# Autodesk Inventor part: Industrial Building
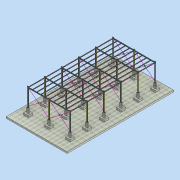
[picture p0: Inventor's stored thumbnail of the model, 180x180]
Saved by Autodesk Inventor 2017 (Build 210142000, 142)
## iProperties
Created: 2018-12
Part Number: Industrial Building
Material: Generic
Document SubType Name: Modeling
Designer: BasilMayyas
Density: 1 g/cm^3
Appearance: Default
Author: BasilMayyas
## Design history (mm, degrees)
derived "Frame0001.iam"
body "Solid1"
node "JIS 350 x 150 x 9 A:1"
node "JIS 350 x 150 x 9 B:1"
node "JIS 350 x 150 x 9 C:1"
node "JIS 250 x 125 x 7.5 AB Tie Beam:1"
node "JIS 250 x 125 x 7.5 BC Tie Beam:1"
node "JIS 350 x 150 x 9 B:2"
node "JIS 350 x 150 x 9 A:2"
node "JIS 350 x 150 x 9 C:2"
node "JIS 350 x 150 x 9 B:3"
node "JIS 350 x 150 x 9 A:3"
node "JIS 350 x 150 x 9 C:3"
node "JIS 350 x 150 x 9 B:4"
node "JIS 350 x 150 x 9 A:4"
node "JIS 350 x 150 x 9 C:4"
node "JIS 350 x 150 x 9 B:5"
node "JIS 350 x 150 x 9 A:5"
node "JIS 350 x 150 x 9 C:5"
node "JIS 350 x 150 x 9 B:6"
node "JIS 350 x 150 x 9 A:6"
node "JIS 350 x 150 x 9 C:6"
node "JIS 250 x 125 x 7.5 AB Tie Beam:2"
node "JIS 250 x 125 x 7.5 AB Tie Beam:3"
node "JIS 250 x 125 x 7.5 AB Tie Beam:4"
node "JIS 250 x 125 x 7.5 AB Tie Beam:5"
node "JIS 250 x 125 x 7.5 AB Tie Beam:6"
node "JIS 250 x 125 x 7.5 BC Tie Beam:2"
node "JIS 250 x 125 x 7.5 BC Tie Beam:3"
node "JIS 250 x 125 x 7.5 BC Tie Beam:4"
node "JIS 250 x 125 x 7.5 BC Tie Beam:5"
node "JIS 250 x 125 x 7.5 BC Tie Beam:6"
node "I350 Base Plate.ipt:1"
node "I350 Base Plate.ipt:2"
node "I350 Base Plate.ipt:3"
node "I350 Base Plate.ipt:4"
node "I350 Base Plate.ipt:5"
node "I350 Base Plate.ipt:6"
node "I350 Base Plate.ipt:7"
node "I350 Base Plate.ipt:8"
node "I350 Base Plate.ipt:9"
node "I350 Base Plate.ipt:10"
node "I350 Base Plate.ipt:11"
node "I350 Base Plate.ipt:12"
node "I350 Base Plate.ipt:13"
node "I350 Base Plate.ipt:14"
node "I350 Base Plate.ipt:15"
node "I350 Base Plate.ipt:16"
node "I350 Base Plate.ipt:17"
node "I350 Base Plate.ipt:18"
node "I350 Base Plate.ipt:19"
node "I350 Base Plate.ipt:20"
node "I350 Base Plate.ipt:21"
node "I350 Base Plate.ipt:22"
node "I350 Base Plate.ipt:23"
node "I350 Base Plate.ipt:24"
node "I350 Base Plate.ipt:25"
node "I350 Base Plate.ipt:26"
node "I350 Base Plate.ipt:27"
node "I350 Base Plate.ipt:28"
node "I350 Base Plate.ipt:29"
node "I350 Base Plate.ipt:30"
node "I350 Base Plate.ipt:31"
node "I350 Base Plate.ipt:32"
node "I350 Base Plate.ipt:33"
node "I350 Base Plate.ipt:34"
node "I350 Base Plate.ipt:35"
node "I350 Base Plate.ipt:36"
node "JIS 200 x 100 x 7 Roof Support Beam:1"
node "JIS 200 x 100 x 7 Roof Support Beam:2"
node "JIS 200 x 100 x 7 Roof Support Beam:3"
node "JIS 200 x 100 x 7 Roof Support Beam:4"
node "JIS 200 x 100 x 7 Roof Support Beam:5"
node "JIS 200 x 100 x 7 Roof Support Beam:6"
node "JIS 200 x 100 x 7 Roof Support Beam:7"
node "JIS 200 x 100 x 7 Roof Support Beam:8"
node "JIS 200 x 100 x 7 Roof Support Beam:9"
node "JIS 200 x 100 x 7 Roof Support Beam:10"
node "JIS 200 x 100 x 7 Roof Support Beam:11"
node "JIS 200 x 100 x 7 Roof Support Beam:12"
node "JIS 200 x 100 x 7 Roof Support Beam:13"
node "JIS 200 x 100 x 7 Roof Support Beam:14"
node "JIS 200 x 100 x 7 Roof Support Beam:15"
node "JIS 200 x 100 x 7 Roof Support Beam:16"
node "JIS 200 x 100 x 7 Roof Support Beam:17"
node "JIS 200 x 100 x 7 Roof Support Beam:18"
node "JIS 200 x 100 x 7 Roof Support Beam:19"
node "JIS 200 x 100 x 7 Roof Support Beam:20"
node "JIS 200 x 100 x 7 Roof Support Beam:21"
node "JIS 200 x 100 x 7 Roof Support Beam:22"
node "JIS 200 x 100 x 7 Roof Support Beam:23"
node "JIS 200 x 100 x 7 Roof Support Beam:24"
node "JIS 200 x 100 x 7 Roof Support Beam:25"
node "JIS 200 x 100 x 7 Roof Support Beam:26"
node "JIS 200 x 100 x 7 Roof Support Beam:27"
node "JIS 200 x 100 x 7 Roof Support Beam:28"
node "JIS 200 x 100 x 7 Roof Support Beam:29"
node "JIS 200 x 100 x 7 Roof Support Beam:30"
node "JIS 200 x 100 x 7 Roof Support Beam:31"
node "JIS 200 x 100 x 7 Roof Support Beam:32"
node "JIS 200 x 100 x 7 Roof Support Beam:33"
node "JIS 200 x 100 x 7 Roof Support Beam:34"
node "JIS 200 x 100 x 7 Roof Support Beam:35"
node "JIS 200 x 100 x 7 Roof Support Beam:36"
node "JIS 200 x 100 x 7 Roof Support Beam:37"
node "JIS 200 x 100 x 7 Roof Support Beam:38"
node "JIS 200 x 100 x 7 Roof Support Beam:39"
node "JIS 200 x 100 x 7 Roof Support Beam:40"
node "JIS 200 x 100 x 7 Roof Support Beam:41"
node "JIS 200 x 100 x 7 Roof Support Beam:42"
node "JIS 200 x 100 x 7 Roof Support Beam:43"
node "JIS 200 x 100 x 7 Roof Support Beam:44"
node "JIS 200 x 100 x 7 Roof Support Beam:45"
node "JIS 200 x 100 x 7 Roof Support Beam:46"
node "JIS 200 x 100 x 7 Roof Support Beam:47"
node "JIS 200 x 100 x 7 Roof Support Beam:48"
node "JIS 200 x 100 x 7 Roof Support Beam:49"
node "JIS 200 x 100 x 7 Roof Support Beam:50"
node "JIS 200 x 100 x 7 Roof Support Beam:51"
node "JIS 200 x 100 x 7 Roof Support Beam:52"
node "JIS 200 x 100 x 7 Roof Support Beam:53"
node "JIS 200 x 100 x 7 Roof Support Beam:54"
node "JIS 200 x 100 x 7 Roof Support Beam:55"
node "250 Tie Beam fixing Plate.ipt:1"
node "250 Tie Beam fixing Plate.ipt:2"
node "250 Tie Beam fixing Plate.ipt:3"
node "250 Tie Beam fixing Plate.ipt:4"
node "250 Tie Beam fixing Plate.ipt:5"
node "250 Tie Beam fixing Plate.ipt:6"
node "250 Tie Beam fixing Plate.ipt:7"
node "250 Tie Beam fixing Plate.ipt:8"
node "250 Tie Beam fixing Plate.ipt:9"
node "250 Tie Beam fixing Plate.ipt:10"
node "250 Tie Beam fixing Plate.ipt:11"
node "250 Tie Beam fixing Plate.ipt:12"
node "250 Tie Beam fixing Plate.ipt:13"
node "250 Tie Beam fixing Plate.ipt:14"
node "250 Tie Beam fixing Plate.ipt:15"
node "250 Tie Beam fixing Plate.ipt:16"
node "250 Tie Beam fixing Plate.ipt:17"
node "250 Tie Beam fixing Plate.ipt:18"
node "250 Tie Beam fixing Plate.ipt:19"
node "250 Tie Beam fixing Plate.ipt:20"
node "250 Tie Beam fixing Plate.ipt:21"
node "250 Tie Beam fixing Plate.ipt:22"
node "250 Tie Beam fixing Plate.ipt:23"
node "250 Tie Beam fixing Plate.ipt:24"
node "Roof Beam Fiixing Plate.ipt:1"
node "Roof Beam Fiixing Plate.ipt:2"
node "Roof Beam Fiixing Plate.ipt:3"
node "Roof Beam Fiixing Plate.ipt:4"
node "Roof Beam Fiixing Plate.ipt:5"
node "Roof Beam Fiixing Plate.ipt:6"
node "Roof Beam Fiixing Plate.ipt:7"
node "Roof Beam Fiixing Plate.ipt:8"
node "Roof Beam Fiixing Plate.ipt:9"
node "Roof Beam Fiixing Plate.ipt:10"
node "Roof Beam Fiixing Plate.ipt:11"
node "Roof Beam Fiixing Plate.ipt:12"
node "Roof Beam Fiixing Plate.ipt:13"
node "Roof Beam Fiixing Plate.ipt:14"
node "Roof Beam Fiixing Plate.ipt:15"
node "Roof Beam Fiixing Plate.ipt:16"
node "Roof Beam Fiixing Plate.ipt:17"
node "Roof Beam Fiixing Plate.ipt:18"
node "Roof Beam Fiixing Plate.ipt:19"
node "Roof Beam Fiixing Plate.ipt:20"
node "Roof Beam Fiixing Plate.ipt:21"
node "Roof Beam Fiixing Plate.ipt:22"
node "Roof Beam Fiixing Plate.ipt:23"
node "Roof Beam Fiixing Plate.ipt:24"
node "Roof Beam Fiixing Plate.ipt:25"
node "Roof Beam Fiixing Plate.ipt:26"
node "Roof Beam Fiixing Plate.ipt:27"
node "Roof Beam Fiixing Plate.ipt:28"
node "Roof Beam Fiixing Plate.ipt:29"
node "Roof Beam Fiixing Plate.ipt:30"
node "Roof Beam Fiixing Plate.ipt:31"
node "Roof Beam Fiixing Plate.ipt:32"
node "Roof Beam Fiixing Plate.ipt:33"
node "Roof Beam Fiixing Plate.ipt:34"
node "Roof Beam Fiixing Plate.ipt:35"
node "Roof Beam Fiixing Plate.ipt:36"
node "Roof Beam Fiixing Plate.ipt:37"
node "Roof Beam Fiixing Plate.ipt:38"
node "Roof Beam Fiixing Plate.ipt:39"
node "Roof Beam Fiixing Plate.ipt:40"
node "Roof Beam Fiixing Plate.ipt:41"
node "Roof Beam Fiixing Plate.ipt:42"
node "Roof Beam Fiixing Plate.ipt:43"
node "Roof Beam Fiixing Plate.ipt:44"
node "Roof Beam Fiixing Plate.ipt:45"
node "Roof Beam Fiixing Plate.ipt:46"
node "Roof Beam Fiixing Plate.ipt:47"
node "Roof Beam Fiixing Plate.ipt:48"
node "Roof Beam Fiixing Plate.ipt:49"
node "Roof Beam Fiixing Plate.ipt:50"
node "Roof Beam Fiixing Plate.ipt:51"
node "Roof Beam Fiixing Plate.ipt:52"
node "Roof Beam Fiixing Plate.ipt:53"
node "Roof Beam Fiixing Plate.ipt:54"
node "Roof Beam Fiixing Plate.ipt:55"
node "Roof Beam Fiixing Plate.ipt:56"
node "Roof Beam Fiixing Plate.ipt:57"
node "Roof Beam Fiixing Plate.ipt:58"
node "Roof Beam Fiixing Plate.ipt:59"
node "Roof Beam Fiixing Plate.ipt:60"
node "Roof Beam Fiixing Plate.ipt:61"
node "Roof Beam Fiixing Plate.ipt:62"
node "Roof Beam Fiixing Plate.ipt:63"
node "Roof Beam Fiixing Plate.ipt:64"
node "Roof Beam Fiixing Plate.ipt:65"
node "Roof Beam Fiixing Plate.ipt:66"
node "Roof Beam Fiixing Plate.ipt:67"
node "Roof Beam Fiixing Plate.ipt:68"
node "Roof Beam Fiixing Plate.ipt:69"
node "Roof Beam Fiixing Plate.ipt:70"
node "Roof Beam Fiixing Plate.ipt:71"
node "Roof Beam Fiixing Plate.ipt:72"
node "Roof Beam Fiixing Plate.ipt:73"
node "Roof Beam Fiixing Plate.ipt:74"
node "Roof Beam Fiixing Plate.ipt:75"
node "Roof Beam Fiixing Plate.ipt:76"
node "Roof Beam Fiixing Plate.ipt:77"
node "Roof Beam Fiixing Plate.ipt:78"
node "Roof Beam Fiixing Plate.ipt:79"
node "Roof Beam Fiixing Plate.ipt:80"
node "Roof Beam Fiixing Plate.ipt:81"
node "Roof Beam Fiixing Plate.ipt:82"
node "Roof Beam Fiixing Plate.ipt:83"
node "Roof Beam Fiixing Plate.ipt:84"
node "Roof Beam Fiixing Plate.ipt:85"
node "Roof Beam Fiixing Plate.ipt:86"
node "Roof Beam Fiixing Plate.ipt:87"
node "Roof Beam Fiixing Plate.ipt:88"
node "Roof Beam Fiixing Plate.ipt:89"
node "Roof Beam Fiixing Plate.ipt:90"
node "Roof Beam Fiixing Plate.ipt:91"
node "Roof Beam Fiixing Plate.ipt:92"
node "Roof Beam Fiixing Plate.ipt:93"
node "Roof Beam Fiixing Plate.ipt:94"
node "Roof Beam Fiixing Plate.ipt:95"
node "Roof Beam Fiixing Plate.ipt:96"
node "Roof Beam Fiixing Plate.ipt:97"
node "Roof Beam Fiixing Plate.ipt:98"
node "Roof Beam Fiixing Plate.ipt:99"
node "Roof Beam Fiixing Plate.ipt:100"
node "Roof Beam Fiixing Plate.ipt:101"
node "Roof Beam Fiixing Plate.ipt:102"
node "Roof Beam Fiixing Plate.ipt:103"
node "Roof Beam Fiixing Plate.ipt:104"
node "Roof Beam Fiixing Plate.ipt:105"
node "Roof Beam Fiixing Plate.ipt:106"
node "Roof Beam Fiixing Plate.ipt:107"
node "Roof Beam Fiixing Plate.ipt:108"
node "Roof Beam Fiixing Plate.ipt:109"
node "Roof Beam Fiixing Plate.ipt:110"
node "Concrete Base.ipt:2"
node "Bracing Assembly 1.iam:1::Bracing Pipe.ipt:1"
node "Bracing Assembly 1.iam:1::Bracing End Pipe Hinge.ipt:1"
node "Bracing Assembly 1.iam:1::Bracing Hinge.ipt:1"
sketch "Sketch7"
  geometry: 1 further point
node "Bracing Assembly 1.iam:1::Bracing Midd Hinge.ipt:1"
node "Bracing Assembly 1.iam:1::Bracing End Pipe Hinge.ipt:2"
node "Bracing Assembly 1.iam:1::Bracing Pipe.ipt:2"
node "Bracing Assembly 1.iam:1::Bracing End Pipe Hinge.ipt:3"
node "Bracing Assembly 1.iam:1::Bracing End Pipe Hinge.ipt:4"
node "Bracing Assembly 1.iam:1::Bracing Hinge.ipt:2"
sketch "Sketch7_1"
  geometry: 1 further point
node "Bracing Assembly 1.iam:1::Bracing SUB 1.iam:1::Bracing Pipe."
node "Bracing Assembly 1.iam:1::Bracing SUB 1.iam:1::Bracing End P"
node "Bracing Assembly 1.iam:1::Bracing SUB 1.iam:1::Bracing Hinge"
sketch "Sketch7_2"
  geometry: 1 further point
node "Bracing Assembly 1.iam:1::Bracing SUB 1.iam:1::Bracing End P"
node "Bracing Assembly 1.iam:1::Bracing SUB 1.iam:1::Bracing Pipe."
node "Bracing Assembly 1.iam:1::Bracing SUB 1.iam:1::Bracing End P"
node "Bracing Assembly 1.iam:1::Bracing SUB 1.iam:1::Bracing End P"
node "Bracing Assembly 1.iam:1::Bracing SUB 1.iam:1::Bracing Hinge"
sketch "Sketch7_3"
  geometry: 1 further point
node "Bracing Assembly 1.iam:2::Bracing Pipe.ipt:1"
node "Bracing Assembly 1.iam:2::Bracing End Pipe Hinge.ipt:1"
node "Bracing Assembly 1.iam:2::Bracing Hinge.ipt:1"
sketch "Sketch7_4"
  geometry: 1 further point
node "Bracing Assembly 1.iam:2::Bracing Midd Hinge.ipt:1"
node "Bracing Assembly 1.iam:2::Bracing End Pipe Hinge.ipt:2"
node "Bracing Assembly 1.iam:2::Bracing Pipe.ipt:2"
node "Bracing Assembly 1.iam:2::Bracing End Pipe Hinge.ipt:3"
node "Bracing Assembly 1.iam:2::Bracing End Pipe Hinge.ipt:4"
node "Bracing Assembly 1.iam:2::Bracing Hinge.ipt:2"
sketch "Sketch7_5"
  geometry: 1 further point
node "Bracing Assembly 1.iam:2::Bracing SUB 1.iam:1::Bracing Pipe."
node "Bracing Assembly 1.iam:2::Bracing SUB 1.iam:1::Bracing End P"
node "Bracing Assembly 1.iam:2::Bracing SUB 1.iam:1::Bracing Hinge"
sketch "Sketch7_6"
  geometry: 1 further point
node "Bracing Assembly 1.iam:2::Bracing SUB 1.iam:1::Bracing End P"
node "Bracing Assembly 1.iam:2::Bracing SUB 1.iam:1::Bracing Pipe."
node "Bracing Assembly 1.iam:2::Bracing SUB 1.iam:1::Bracing End P"
node "Bracing Assembly 1.iam:2::Bracing SUB 1.iam:1::Bracing End P"
node "Bracing Assembly 1.iam:2::Bracing SUB 1.iam:1::Bracing Hinge"
sketch "Sketch7_7"
  geometry: 1 further point
node "Bracing Assembly 1.iam:3::Bracing Pipe.ipt:1"
node "Bracing Assembly 1.iam:3::Bracing End Pipe Hinge.ipt:1"
node "Bracing Assembly 1.iam:3::Bracing Hinge.ipt:1"
sketch "Sketch7_8"
  geometry: 1 further point
node "Bracing Assembly 1.iam:3::Bracing Midd Hinge.ipt:1"
node "Bracing Assembly 1.iam:3::Bracing End Pipe Hinge.ipt:2"
node "Bracing Assembly 1.iam:3::Bracing Pipe.ipt:2"
node "Bracing Assembly 1.iam:3::Bracing End Pipe Hinge.ipt:3"
node "Bracing Assembly 1.iam:3::Bracing End Pipe Hinge.ipt:4"
node "Bracing Assembly 1.iam:3::Bracing Hinge.ipt:2"
sketch "Sketch7_9"
  geometry: 1 further point
node "Bracing Assembly 1.iam:3::Bracing SUB 1.iam:1::Bracing Pipe."
node "Bracing Assembly 1.iam:3::Bracing SUB 1.iam:1::Bracing End P"
node "Bracing Assembly 1.iam:3::Bracing SUB 1.iam:1::Bracing Hinge"
sketch "Sketch7_10"
  geometry: 1 further point
node "Bracing Assembly 1.iam:3::Bracing SUB 1.iam:1::Bracing End P"
node "Bracing Assembly 1.iam:3::Bracing SUB 1.iam:1::Bracing Pipe."
node "Bracing Assembly 1.iam:3::Bracing SUB 1.iam:1::Bracing End P"
node "Bracing Assembly 1.iam:3::Bracing SUB 1.iam:1::Bracing End P"
node "Bracing Assembly 1.iam:3::Bracing SUB 1.iam:1::Bracing Hinge"
sketch "Sketch7_11"
  geometry: 1 further point
node "Bracing Assembly 1.iam:4::Bracing Pipe.ipt:1"
node "Bracing Assembly 1.iam:4::Bracing End Pipe Hinge.ipt:1"
node "Bracing Assembly 1.iam:4::Bracing Hinge.ipt:1"
sketch "Sketch7_12"
  geometry: 1 further point
node "Bracing Assembly 1.iam:4::Bracing Midd Hinge.ipt:1"
node "Bracing Assembly 1.iam:4::Bracing End Pipe Hinge.ipt:2"
node "Bracing Assembly 1.iam:4::Bracing Pipe.ipt:2"
node "Bracing Assembly 1.iam:4::Bracing End Pipe Hinge.ipt:3"
node "Bracing Assembly 1.iam:4::Bracing End Pipe Hinge.ipt:4"
node "Bracing Assembly 1.iam:4::Bracing Hinge.ipt:2"
sketch "Sketch7_13"
  geometry: 1 further point
node "Bracing Assembly 1.iam:4::Bracing SUB 1.iam:1::Bracing Pipe."
node "Bracing Assembly 1.iam:4::Bracing SUB 1.iam:1::Bracing End P"
node "Bracing Assembly 1.iam:4::Bracing SUB 1.iam:1::Bracing Hinge"
sketch "Sketch7_14"
  geometry: 1 further point
node "Bracing Assembly 1.iam:4::Bracing SUB 1.iam:1::Bracing End P"
node "Bracing Assembly 1.iam:4::Bracing SUB 1.iam:1::Bracing Pipe."
node "Bracing Assembly 1.iam:4::Bracing SUB 1.iam:1::Bracing End P"
node "Bracing Assembly 1.iam:4::Bracing SUB 1.iam:1::Bracing End P"
node "Bracing Assembly 1.iam:4::Bracing SUB 1.iam:1::Bracing Hinge"
sketch "Sketch7_15"
  geometry: 1 further point
node "Bracing Assembly 1.iam:5::Bracing Pipe.ipt:1"
node "Bracing Assembly 1.iam:5::Bracing End Pipe Hinge.ipt:1"
node "Bracing Assembly 1.iam:5::Bracing Hinge.ipt:1"
sketch "Sketch7_16"
  geometry: 1 further point
node "Bracing Assembly 1.iam:5::Bracing Midd Hinge.ipt:1"
node "Bracing Assembly 1.iam:5::Bracing End Pipe Hinge.ipt:2"
node "Bracing Assembly 1.iam:5::Bracing Pipe.ipt:2"
node "Bracing Assembly 1.iam:5::Bracing End Pipe Hinge.ipt:3"
node "Bracing Assembly 1.iam:5::Bracing End Pipe Hinge.ipt:4"
node "Bracing Assembly 1.iam:5::Bracing Hinge.ipt:2"
sketch "Sketch7_17"
  geometry: 1 further point
node "Bracing Assembly 1.iam:5::Bracing SUB 1.iam:1::Bracing Pipe."
node "Bracing Assembly 1.iam:5::Bracing SUB 1.iam:1::Bracing End P"
node "Bracing Assembly 1.iam:5::Bracing SUB 1.iam:1::Bracing Hinge"
sketch "Sketch7_18"
  geometry: 1 further point
node "Bracing Assembly 1.iam:5::Bracing SUB 1.iam:1::Bracing End P"
node "Bracing Assembly 1.iam:5::Bracing SUB 1.iam:1::Bracing Pipe."
node "Bracing Assembly 1.iam:5::Bracing SUB 1.iam:1::Bracing End P"
node "Bracing Assembly 1.iam:5::Bracing SUB 1.iam:1::Bracing End P"
node "Bracing Assembly 1.iam:5::Bracing SUB 1.iam:1::Bracing Hinge"
sketch "Sketch7_19"
  geometry: 1 further point
node "Bracing Assembly 1.iam:6::Bracing Pipe.ipt:1"
node "Bracing Assembly 1.iam:6::Bracing End Pipe Hinge.ipt:1"
node "Bracing Assembly 1.iam:6::Bracing Hinge.ipt:1"
sketch "Sketch7_20"
  geometry: 1 further point
node "Bracing Assembly 1.iam:6::Bracing Midd Hinge.ipt:1"
node "Bracing Assembly 1.iam:6::Bracing End Pipe Hinge.ipt:2"
node "Bracing Assembly 1.iam:6::Bracing Pipe.ipt:2"
node "Bracing Assembly 1.iam:6::Bracing End Pipe Hinge.ipt:3"
node "Bracing Assembly 1.iam:6::Bracing End Pipe Hinge.ipt:4"
node "Bracing Assembly 1.iam:6::Bracing Hinge.ipt:2"
sketch "Sketch7_21"
  geometry: 1 further point
node "Bracing Assembly 1.iam:6::Bracing SUB 1.iam:1::Bracing Pipe."
node "Bracing Assembly 1.iam:6::Bracing SUB 1.iam:1::Bracing End P"
node "Bracing Assembly 1.iam:6::Bracing SUB 1.iam:1::Bracing Hinge"
sketch "Sketch7_22"
  geometry: 1 further point
node "Bracing Assembly 1.iam:6::Bracing SUB 1.iam:1::Bracing End P"
node "Bracing Assembly 1.iam:6::Bracing SUB 1.iam:1::Bracing Pipe."
node "Bracing Assembly 1.iam:6::Bracing SUB 1.iam:1::Bracing End P"
node "Bracing Assembly 1.iam:6::Bracing SUB 1.iam:1::Bracing End P"
node "Bracing Assembly 1.iam:6::Bracing SUB 1.iam:1::Bracing Hinge"
sketch "Sketch7_23"
  geometry: 1 further point
node "Bracing Assembly 1.iam:7::Bracing Pipe.ipt:1"
node "Bracing Assembly 1.iam:7::Bracing End Pipe Hinge.ipt:1"
node "Bracing Assembly 1.iam:7::Bracing Hinge.ipt:1"
sketch "Sketch7_24"
  geometry: 1 further point
node "Bracing Assembly 1.iam:7::Bracing Midd Hinge.ipt:1"
node "Bracing Assembly 1.iam:7::Bracing End Pipe Hinge.ipt:2"
node "Bracing Assembly 1.iam:7::Bracing Pipe.ipt:2"
node "Bracing Assembly 1.iam:7::Bracing End Pipe Hinge.ipt:3"
node "Bracing Assembly 1.iam:7::Bracing End Pipe Hinge.ipt:4"
node "Bracing Assembly 1.iam:7::Bracing Hinge.ipt:2"
sketch "Sketch7_25"
  geometry: 1 further point
node "Bracing Assembly 1.iam:7::Bracing SUB 1.iam:1::Bracing Pipe."
node "Bracing Assembly 1.iam:7::Bracing SUB 1.iam:1::Bracing End P"
node "Bracing Assembly 1.iam:7::Bracing SUB 1.iam:1::Bracing Hinge"
sketch "Sketch7_26"
  geometry: 1 further point
node "Bracing Assembly 1.iam:7::Bracing SUB 1.iam:1::Bracing End P"
node "Bracing Assembly 1.iam:7::Bracing SUB 1.iam:1::Bracing Pipe."
node "Bracing Assembly 1.iam:7::Bracing SUB 1.iam:1::Bracing End P"
node "Bracing Assembly 1.iam:7::Bracing SUB 1.iam:1::Bracing End P"
node "Bracing Assembly 1.iam:7::Bracing SUB 1.iam:1::Bracing Hinge"
sketch "Sketch7_27"
  geometry: 1 further point
node "Bracing Assembly 1.iam:8::Bracing Pipe.ipt:1"
node "Bracing Assembly 1.iam:8::Bracing End Pipe Hinge.ipt:1"
node "Bracing Assembly 1.iam:8::Bracing Hinge.ipt:1"
sketch "Sketch7_28"
  geometry: 1 further point
node "Bracing Assembly 1.iam:8::Bracing Midd Hinge.ipt:1"
node "Bracing Assembly 1.iam:8::Bracing End Pipe Hinge.ipt:2"
node "Bracing Assembly 1.iam:8::Bracing Pipe.ipt:2"
node "Bracing Assembly 1.iam:8::Bracing End Pipe Hinge.ipt:3"
node "Bracing Assembly 1.iam:8::Bracing End Pipe Hinge.ipt:4"
node "Bracing Assembly 1.iam:8::Bracing Hinge.ipt:2"
sketch "Sketch7_29"
  geometry: 1 further point
node "Bracing Assembly 1.iam:8::Bracing SUB 1.iam:1::Bracing Pipe."
node "Bracing Assembly 1.iam:8::Bracing SUB 1.iam:1::Bracing End P"
node "Bracing Assembly 1.iam:8::Bracing SUB 1.iam:1::Bracing Hinge"
sketch "Sketch7_30"
  geometry: 1 further point
node "Bracing Assembly 1.iam:8::Bracing SUB 1.iam:1::Bracing End P"
node "Bracing Assembly 1.iam:8::Bracing SUB 1.iam:1::Bracing Pipe."
node "Bracing Assembly 1.iam:8::Bracing SUB 1.iam:1::Bracing End P"
node "Bracing Assembly 1.iam:8::Bracing SUB 1.iam:1::Bracing End P"
node "Bracing Assembly 1.iam:8::Bracing SUB 1.iam:1::Bracing Hinge"
sketch "Sketch7_31"
  geometry: 1 further point
other parameters: "G_L_30" = 5501, "G_L_31" = 5501, "G_L_32" = 5501, "G_L_33" = 5501, "G_L_34" = 5501, "G_L_35" = 5501, "G_L_36" = 5501, "G_L_37" = 5501, "G_L_38" = 5501, "G_L_39" = 5501, "G_L_40" = 5501, "G_L_41" = 5501, "G_L_42" = 5501, "G_L_43" = 5501, "G_L_44" = 5501, "G_L_45" = 5501, "G_L_46" = 5501, "G_L_47" = 5501, "G_L_48" = 5501, "G_L_49" = 5501, "G_L_50" = 5501, "G_L_51" = 5501, "G_L_52" = 5501, "G_L_53" = 5501, "G_L_54" = 5501, "G_L_55" = 5501, "G_L_56" = 5501, "G_L_57" = 5501, "G_L_58" = 5501, "G_L_59" = 5501, "G_L_60" = 5501, "G_L_61" = 5501, "G_L_62" = 5501, "G_L_63" = 5501, "G_L_64" = 5501, "G_L_65" = 5501, "G_L_66" = 5501, "G_L_67" = 5501, "G_L_68" = 5501, "G_L_69" = 5501, "G_L_70" = 5501, "G_L_71" = 5501, "G_L_72" = 5501, "G_L_73" = 5501, "G_L_74" = 5501, "G_L_75" = 5501, "G_L_76" = 5501, "G_L_77" = 5501, "G_L_78" = 5501, "G_L_79" = 5501, "G_L_80" = 5501, "G_L_81" = 5501, "G_L_82" = 5501, "G_L_83" = 5501, "G_L_84" = 5501
